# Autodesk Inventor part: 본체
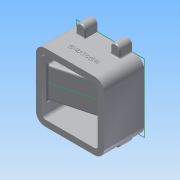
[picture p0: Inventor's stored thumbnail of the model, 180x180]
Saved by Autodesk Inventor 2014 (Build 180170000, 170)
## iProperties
Created: 2018-01
Part Number: 본체
Material: 알루미늄 6061
Document SubType Name: Modeling
Designer: net
Mass: 998.942 g
Surface Area: 839.391 cm^2
Volume: 368.613 cm^3
Density: 2.71 g/cm^3
Appearance: 알루미늄 - 평지
Author: net
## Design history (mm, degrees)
sketch "스케치1"
  geometry: L1 (-55, -55)-(55, -55); L2 (55, -55)-(55, 55); L3 (55, 55)-(-55, 55); L4 (-55, 55)-(-55, -55); L5 (-55, -55)-(55, 55); L6 (55, -55)-(-55, 55); 1 further point
  constraints: 12 end point, 2 midpoint, 2 parallel, 1 horizontal, 1 perpendicular
  dimensions: "d0" = 110 distance of L3.end L2.end; "d1" = 110 distance of L2.end L1.end
extrude "돌출1" new body sketch "스케치1" distance "d2" = 65; taper "d3" = 0 deg
sketch "스케치2"
  geometry: L1 (55, 55)-(-55, 55) reference; L2 (-55, 55)-(-55, -55) reference; L3 (-55, -55)-(55, -55) reference; L4 (55, -55)-(55, 55) reference; 1 further point
sketch "스케치3"
  geometry: L1 (-45, -45)-(45, -45); L2 (45, -45)-(45, 45); L3 (45, 45)-(-45, 45); L4 (-45, 45)-(-45, -45); L5 (-45, -45)-(45, 45); L6 (45, -45)-(-45, 45); 1 further point
  constraints: 12 end point, 2 midpoint, 2 parallel, 1 horizontal, 1 perpendicular
  dimensions: "d4" = 90 distance of L3.end L2.end; "d5" = 90 distance of L2.end L1.end
extrude "돌출2" cut sketch "스케치3" distance "d6" = 65; taper "d7" = 0 deg
sketch "스케치4"
  geometry: L1 (55, 55)-(-55, 55) reference; L2 (-55, 55)-(-55, -55) reference; L3 (-55, -55)-(55, -55) reference; L4 (-55, 0)-(-55, 25); L5 (-35.5, 65)-(-35.5, 55); L6 (-20.5, 65)-(-20.5, 55); L7 (0, 55)-(0, -55); L8 (-28, 65)-(28, 65); L9 (20.5, 65)-(20.5, 55); L10 (35.5, 65)-(35.5, 55); L11 (-55, -55)-(-28, -55); L12 (-28, -55)-(-28, -65); L13 (-35.5, -65)-(-35.5, -55); L14 (-20.5, -65)-(-20.5, -55); L15 (35.5, -65)-(35.5, -55); L16 (20.5, -65)-(20.5, -55); A1 r 7.5 centre (-28, 65) between (-20.5, 65) and (-35.5, 65); A2 r 7.5 centre (28, 65) between (35.5, 65) and (20.5, 65); A3 r 7.5 centre (-28, -65) between (-35.5, -65) and (-20.5, -65); A4 r 7.5 centre (28, -65) between (20.5, -65) and (35.5, -65); 1 further point
  constraints: 26 end point, 11 point on line, 8 point on circle, 8 tangent, 6 perpendicular, 4 centre point, 3 midpoint, 3 parallel, 2 coincident
  dimensions: "d9" = 25 distance of L4.start L4.end; "d11" = 27 distance from line of L2 L8.start; "d12" = 7.5 radius of A1; "d13" = 10 distance of L6.start L6.end; "d14" = 56 distance of L8.start L8.end; "d15" = 15 diameter of A2; "d16" = 27 distance of L2.end L11.end; "d17" = 10 distance of L11.end L12.end; "d18" = 15 diameter of A3; "d20" = 15 diameter of A4
extrude "돌출3" join sketch "스케치4" distance "d21" = 20; taper "d22" = 0 deg
sketch "스케치5"
  geometry: L1 (-45, 0)-(-45, 65) reference; L2 (-45, 8.564)-(35, 30); L3 (-45, 8.564)-(-45, 65); L4 (55, 0)-(-55, 0) reference; L5 (-45, 8.564)-(-55, 8.564); L6 (-55, 8.564)-(-55, 26.564); L7 (-55, 26.564)-(-45, 26.564); L8 (-45, 26.564)-(-6.286, 36.938); L9 (-6.286, 36.938)-(-6.286, 65); L10 (-45, 65)-(35, 65); L11 (35, 65)-(35, 30); 2 further points
  constraints: 18 end point, 3 perpendicular, 3 point on line, 2 parallel, 1 collinear
  dimensions: "d23" = 105 deg angle of L1 L2; "d25" = 18 distance of L5.end L6.end; "d26" = 75 deg angle of L1 L8 (derived); "d28" = 20 distance of point (55, 65) L10.end; "d29" = 30 distance from line of L4 L2.end
extrude "돌출4" join sketch "스케치5" stored distance "d30" = 50; taper "d31" = 0 deg
sketch "스케치6"
  geometry: 1 further point
sketch "스케치7"
  geometry: L1 (0, 65)-(110, 65) reference; C1 r 7.5 at (55, 65); 1 further point
  constraints: 1 centre point, 1 midpoint
  dimensions: "d32" = 15 diameter of C1
extrude "돌출5" cut sketch "스케치7" distance "d33" = 19; taper "d34" = 0 deg
sketch "스케치8"
  geometry: L1 (47.5, 65)-(62.5, 65) reference; A1 r 7.5 centre (55, 65) between (47.5, 65) and (62.5, 65) reference; 1 further point
sketch "스케치9"
  geometry: L1 (47.5, 65)-(62.5, 65) reference; C1 r 16 at (55, 65); A1 r 7.5 centre (55, 65) between (47.5, 65) and (62.5, 65) reference; 1 further point
  constraints: 1 centre point, 1 coincident
  dimensions: "d36" = 32 diameter of C1
extrude "돌출6" cut sketch "스케치9" distance "d37" = 14; taper "d38" = 0 deg
extrude "돌출7" cut sketch "스케치8" distance "d39" = 14; taper "d40" = 0 deg
sketch "스케치10"
  geometry: L1 (39, 65)-(71, 65) reference; C1 r 20 at (55, 65); A1 r 16 centre (55, 65) between (39, 65) and (71, 65) reference; 1 further point
  constraints: 1 centre point, 1 coincident
  dimensions: "d41" = 40 diameter of C1
extrude "돌출8" cut sketch "스케치10" distance "d42" = 47; taper "d43" = 0 deg
sketch "스케치11"
  geometry: L1 (39, 65)-(71, 65) reference; A1 r 16 centre (55, 65) between (39, 65) and (71, 65) reference; 1 further point
extrude "돌출9" cut sketch "스케치11" distance "d44" = 47; taper "d45" = 0 deg
sketch "스케치14"
  geometry: 1 further point
node "작업 평면3"
sketch "스케치16"
  geometry: 1 further point
sketch "스케치17"
  geometry: L1 (3.5, 15)-(40.5, 15); L2 (40.5, 15)-(40.5, -15); L3 (40.5, -15)-(3.5, -15); L4 (3.5, -15)-(3.5, 15); L5 (3.5, 15)-(40.5, -15); L6 (40.5, 15)-(3.5, -15); 1 further point
  constraints: 12 end point, 2 midpoint, 2 parallel, 1 horizontal, 1 perpendicular
  dimensions: "d52" = 37 distance of L2.end L3.end; "d53" = 30 distance of L1.end L2.end
extrude "돌출11" cut sketch "스케치17" distance "d54" = 13; taper "d55" = 0 deg; dims "d56" = 30, "d57" = 0
sketch "스케치18"
  geometry: 1 further point
sketch "스케치19"
  geometry: L1 (-18.5, 32)-(-18.5, 51.771) reference; L2 (-18.5, 32)-(-18.5, 37.747); L3 (-18.5, 37.747)-(-55, 27.967); L4 (-18.5, 37.747)-(-55, 27.967); L5 (-18.5, 51.771)-(18.5, 51.771) reference; L6 (-18.5, 32)-(-18.5, 51.771) reference; L7 (-18.5, 32)-(18.5, 32) reference; L8 (18.5, 32)-(18.5, 51.771) reference; L9 (18.5, 32)-(18.5, 30.568); L10 (18.5, 30.568)-(-55, 9.967); L11 (-55, 27.967)-(-55, 9.967); L12 (-18.5, 32)-(18.5, 32); L13 (-55, 27.967)-(-18.5, 37.747); L14 (-18.5, 32)-(-18.5, 37.747); L15 (-18.5, 32)-(18.5, 32); L16 (18.5, 32)-(18.5, 30.568); L17 (18.5, 30.568)-(-55, 9.967); L18 (-55, 9.967)-(-55, 27.967); 1 further point
  constraints: 26 end point, 7 collinear, 2 perpendicular
  node "투영된 루프2"
sketch "스케치20"
  geometry: C1 r 15 at (55, 65); A1 r 20 centre (55, 65) between (35, 65) and (75, 65) reference; 1 further point
  constraints: 1 centre point, 1 coincident
  dimensions: "d58" = 20 radius of A1 (derived); "d59" = 30 diameter of C1 (derived)
extrude "돌출12" cut sketch "스케치20" distance "d60" = 5; taper "d61" = 0 deg
extrude "돌출13" cut sketch "스케치19" stored distance "d62" = 15; taper "d63" = 0 deg
sketch "스케치21"
  geometry: L1 (3.5, 7.5)-(40.5, 7.5) reference; L2 (40.5, 15)-(40.5, 7.5) reference; L3 (3.5, 15)-(40.5, 15) reference; L4 (3.5, 7.5)-(3.5, 15) reference; 1 further point
sketch "스케치22"
  geometry: L1 (40.5, -7.5)-(3.5, -7.5) reference; L2 (3.5, -15)-(3.5, -7.5) reference; L3 (40.5, -15)-(3.5, -15) reference; L4 (40.5, -7.5)-(40.5, -15) reference; 1 further point
extrude "돌출14" cut sketch "스케치21" stored distance "d64" = 15; taper "d65" = 0 deg
sketch "스케치23"
  geometry: L1 (35, 30)-(-45, 8.564) reference; L2 (-55, 0)-(-55, 65) reference; L3 (18.5, 30.568)-(-18.5, 20.197) reference; 1 further point
sketch "스케치24"
  geometry: L1 (0, 22.5)-(0, 0) reference; L2 (0, 22.5)-(-38.426, 22.5) reference; L3 (-38.426, 22.5)-(-38.426, 15) reference; L4 (-38.426, 15)-(-76.333, 15) reference; L5 (-76.333, 0)-(-76.333, 15) reference; L6 (-76.333, 0)-(0, 0) reference; 1 further point
sketch "스케치25"
  geometry: L1 (47.5, 9.967)-(47.5, 27.967) reference; L2 (47.5, 27.967)-(62.5, 27.967) reference; L3 (62.5, 27.967)-(62.5, 9.967) reference; L4 (62.5, 9.967)-(47.5, 9.967) reference; L5 (55, 27.967)-(55, 9.967); L6 (70, 9.967)-(40, 9.967); L7 (40, 9.967)-(40, 27.967); L8 (40, 27.967)-(70, 27.967); L9 (70, 27.967)-(70, 9.967); L10 (70, 9.967)-(40, 27.967); L11 (40, 9.967)-(70, 27.967); 2 further points
  constraints: 14 end point, 5 midpoint, 2 parallel, 1 horizontal, 1 perpendicular, 1 point on line
  dimensions: "d66" = 30 distance of L7.end L8.end
extrude "돌출15" cut sketch "스케치25" stored distance "d67" = 15; taper "d68" = 0 deg
sketch "스케치26"
  geometry: L1 (36.5, 7.5)-(36.5, 0) reference; L2 (0, 7.5)-(36.5, 7.5) reference; L3 (0, 0)-(0, 7.5) reference; L4 (0, 0)-(36.5, 0) reference; 1 further point
extrude "돌출16" cut sketch "스케치26" stored distance "d69" = 15; taper "d70" = 0 deg
sketch "스케치27"
  geometry: L1 (64.22, 7.5)-(64.22, 0) reference; L2 (0, 7.5)-(64.22, 7.5) reference; L3 (0, 0)-(0, 7.5) reference; L4 (64.22, 0)-(0, 0) reference; 1 further point
extrude "돌출17" cut sketch "스케치27" stored distance "d71" = 15; taper "d72" = 0 deg
sketch "스케치28"
  geometry: L1 (31.22, -7.5)-(31.22, -15) reference; L2 (40.5, -15)-(31.22, -15) reference; L3 (40.5, -7.5)-(40.5, -15) reference; L4 (40.5, -7.5)-(31.22, -7.5) reference; 1 further point
extrude "돌출18" cut sketch "스케치22" stored distance "d73" = 15; taper "d74" = 0 deg
sketch "스케치29"
  geometry: A1 r 7.5 centre (-28, -65) between (-35.5, -65) and (-20.5, -65) reference; A2 r 7.5 centre (28, -65) between (20.5, -65) and (35.5, -65) reference; A3 r 7.5 centre (28, 65) between (35.5, 65) and (20.5, 65) reference; A4 r 7.5 centre (-28, 65) between (-20.5, 65) and (-35.5, 65) reference; 1 further point
hole "구멍1" sketch "스케치29" at (-28, 65), (28, 65), (28, -65), (-28, -65) diameter "d75" = 3.242; stored, may be unused: countersink angle "d79" = 90 deg, drill point angle "d81" = 118 deg; dims "d76" = 9, "d77" = 4, "d78" = 2, "d80" = 11
fillet "모깎기1" dims "d82" = 15
fillet "모깎기2" dims "d83" = 3
fillet "모깎기3" dims "d84" = 1
fillet "모깎기4" dims "d85" = 3
fillet "모깎기5" dims "d86" = 5
fillet "모깎기6" dims "d87" = 3
fillet "모깎기7" dims "d88" = 3
chamfer "모따기1" distance "d89" = 1; stored, may be unused: second distance "d90" = 2, angle "d91" = 45 deg
chamfer "모따기2" distance "d92" = 1; stored, may be unused: second distance "d93" = 2, angle "d94" = 45 deg
sketch "스케치30"
  geometry: L1 (-17.958, -22.32)-(59.863, -22.32); L2 (59.863, -22.32)-(59.863, -62.588); L3 (59.863, -62.588)-(-17.958, -62.588); L4 (-17.958, -62.588)-(-17.958, -22.32); 1 further point
  constraints: 2 other
feature "엠보싱1" sketch "스케치30" dims "d4" = 90, "d5" = 90, "d95" = 0.5, "d96" = 0
fillet "모깎기8" dims "d97" = 2
node "솔리드1"
